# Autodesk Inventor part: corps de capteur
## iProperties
Created: 2007-07
Part Number: corps de capteur
Document SubType Name: Modeling
Designer: EF
Density: 1 g/cm^3
Mass: 4.39659 g
Surface Area: 21.4513 cm^2
Volume: 4.39659 cm^3
Author: EF
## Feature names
1. Extrusion2
2. Hole2
3. Hole1
4. Fillet4
5. Fillet3
6. Fillet2
7. Fillet1
8. Extrusion4
